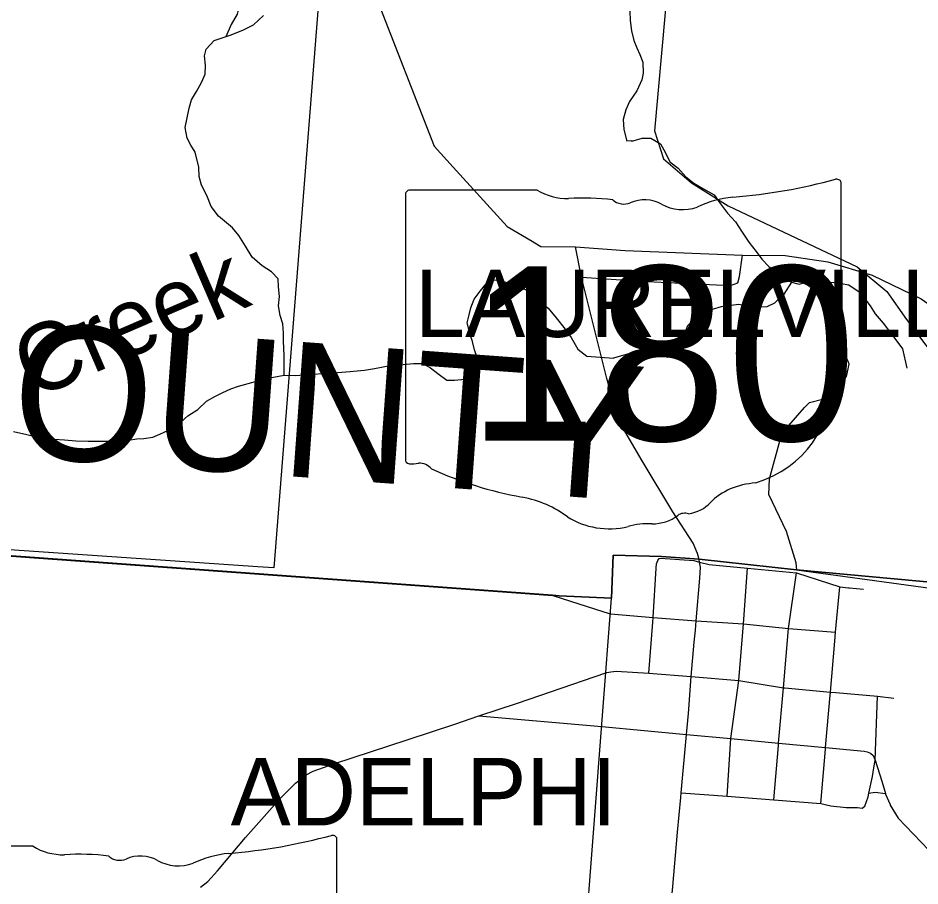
# Model space of a CAD drawing. Extents: x 0 to 42.5, y 0 to 22.
# Drawn here: x 7.502 to 8.135, y 15.405 to 16.014 of the extents above; entities that cross this region are included whole.
import ezdxf

# ---------------------------------------------------------------- set-up
doc = ezdxf.new("R2010")
doc.units = 0
for name, color, linetype in [('GM_X_City_Street', 7, 'Continuous'), ('GM_X_Corporation', 7, 'Continuous'), ('GM_X_Corporation_Text', 7, 'Continuous'), ('GM_X_County_Road', 7, 'Continuous'), ('GM_X_County_Text', 7, 'Continuous'), ('GM_X_Interchange_Ramps', 7, 'Continuous'), ('GM_X_Major_River', 7, 'Continuous'), ('GM_X_Minor_River', 7, 'Continuous'), ('GM_X_Minor_River_Text', 7, 'Continuous'), ('GM_X_Rail_Line', 7, 'Continuous'), ('GM_X_Section', 7, 'Continuous'), ('GM_X_State_Location', 7, 'Continuous'), ('GM_X_State_Route', 7, 'Continuous'), ('GM_X_State_Shield', 7, 'Continuous'), ('GM_X_Township', 7, 'Continuous'), ('GM_X_Township_Road', 7, 'Continuous'), ('SH_Cut_Line', 7, 'Continuous')]:
    doc.layers.add(name, color=color, linetype=linetype)

msp = doc.modelspace()

# ---------------------------------------------------------------- linework, layer by layer
at = {"layer": 'GM_X_City_Street'}
for points in [[(7.94946, 15.62782), (7.94964, 15.63083), (7.95056, 15.63326), (7.9517, 15.63451), (7.95243, 15.63492), (7.97602, 15.63321)], [(7.97602, 15.63321), (7.97995, 15.63207), (7.98677, 15.63034), (8.01368, 15.62775), (8.04805, 15.62451), (8.07833, 15.61475), (8.08456, 15.61412)], [(7.94425, 15.55408), (7.94725, 15.58987), (7.94745, 15.5932), (7.94946, 15.62782)], [(7.99931, 15.46769), (8.0019, 15.50818), (8.0074, 15.54903), (8.01084, 15.58864), (8.01368, 15.62775)], [(8.03206, 15.46517), (8.03532, 15.50341), (8.03545, 15.50498), (8.03876, 15.54379), (8.04231, 15.5855), (8.04805, 15.62451)], [(8.07483, 15.57664), (8.07537, 15.58282), (8.07833, 15.61475)], [(8.08456, 15.61412), (8.08508, 15.61407), (8.09512, 15.61305)], [(7.97758, 15.59076), (8.01084, 15.58864), (8.04231, 15.5855), (8.07537, 15.58282)], [(8.07155, 15.53864), (8.07174, 15.54083), (8.07483, 15.57664)], [(7.97399, 15.55167), (8.0074, 15.54903), (8.03876, 15.54379), (8.03974, 15.54371)], [(8.03974, 15.54371), (8.07174, 15.54083), (8.07559, 15.54048), (8.10479, 15.53785), (8.11637, 15.53655)], [(8.06499, 15.46264), (8.06827, 15.50064), (8.06837, 15.50184), (8.07155, 15.53864)], [(8.10237, 15.48771), (8.10308, 15.4916), (8.10313, 15.49293), (8.10479, 15.53785)], [(7.91137, 15.51661), (7.97081, 15.51115), (8.0019, 15.50818), (8.03545, 15.50498), (8.06837, 15.50184), (8.09556, 15.49924), (8.09764, 15.49898), (8.09988, 15.49796), (8.10172, 15.4962), (8.10313, 15.49293), (8.10795, 15.47835), (8.11036, 15.46966), (8.1105, 15.46915), (8.11366, 15.46188), (8.11385, 15.46146), (8.11924, 15.45237), (8.15691, 15.41289)], [(8.096, 15.4607), (8.0983, 15.46727), (8.09882, 15.46978), (8.10124, 15.4816), (8.10237, 15.48771)], [(7.96702, 15.47016), (7.99931, 15.46769), (8.03206, 15.46517), (8.06499, 15.46264), (8.07213, 15.46089), (8.08289, 15.45978), (8.09085, 15.45972), (8.09407, 15.45943), (8.096, 15.4607)], [(8.09882, 15.46978), (8.10315, 15.47053), (8.11036, 15.46966)]]:
    msp.add_lwpolyline(points, dxfattribs=at)
at = {"layer": 'GM_X_Corporation'}
msp.add_lwpolyline([(7.91921, 15.63683), (7.95331, 15.6361), (7.97957, 15.63417), (8.04805, 15.62672), (8.16418, 15.61064), (8.16271, 15.59296), (8.14602, 15.34154), (7.89922, 15.35961), (7.91813, 15.60669)], close=True, dxfattribs=at)
at = {"layer": 'GM_X_County_Road'}
for p, q in [((7.42284, 15.64165), (7.87685, 15.60852)), ((7.87685, 15.60852), (7.91279, 15.59711))]:
    msp.add_line(p, q, dxfattribs=at)
msp.add_lwpolyline([(7.91279, 15.59711), (7.91741, 15.59564), (7.94745, 15.5932), (7.97758, 15.59076)], dxfattribs=at)
at = {"layer": 'GM_X_Interchange_Ramps'}
msp.add_lwpolyline([(5.08492, 14.1), (8.06989, 14.1), (8.07009, 14.10263), (8.07289, 14.12804), (8.09551, 14.48695), (8.1568, 15.41315), (8.16884, 15.59509), (8.16995, 15.61544), (8.04805, 15.62672), (7.97957, 15.63417), (7.95331, 15.6361), (7.91921, 15.63683), (7.91813, 15.60669), (7.88151, 15.60844), (7.87674, 15.60879), (7.42273, 15.64192), (7.26665, 15.65331), (5.92916, 15.74982)], dxfattribs=at)
at = {"layer": 'GM_X_Major_River'}
for points in [[(7.68834, 15.76319), (7.68834, 15.76319), (7.68835, 15.77721), (7.68817, 15.78195), (7.688, 15.78746), (7.68801, 15.79277), (7.68745, 15.79923), (7.68557, 15.80512), (7.68445, 15.81196), (7.68503, 15.81841), (7.68429, 15.82524), (7.68412, 15.83094), (7.67958, 15.8359), (7.67295, 15.8401), (7.66595, 15.84621), (7.66122, 15.85383), (7.6565, 15.86125), (7.65215, 15.86678), (7.64231, 15.8748), (7.63721, 15.88166), (7.634, 15.88945), (7.63041, 15.89668), (7.62872, 15.90276), (7.62855, 15.90922), (7.62592, 15.91986), (7.6229, 15.92481), (7.62025, 15.92957), (7.61894, 15.93717), (7.62029, 15.94399), (7.62163, 15.95063), (7.62335, 15.95669), (7.62678, 15.96237), (7.63039, 15.96881), (7.63287, 15.97468), (7.63308, 15.98094), (7.63253, 15.98739), (7.63367, 15.99213), (7.63919, 15.99818), (7.64564, 16.00024), (7.65039, 16.00192), (7.65931, 16.00548), (7.6669, 16.00924), (7.67393, 16.01566)], [(7.68834, 15.76319), (7.69628, 15.76312), (7.70235, 15.76347), (7.70918, 15.76401), (7.71506, 15.76436), (7.72113, 15.76471), (7.72587, 15.76525), (7.73478, 15.76597), (7.73972, 15.76632), (7.74465, 15.76687), (7.75167, 15.76797), (7.7566, 15.7689), (7.76134, 15.76982), (7.76665, 15.77018), (7.77196, 15.77072), (7.77917, 15.77145), (7.78581, 15.7716), (7.79111, 15.76835), (7.79622, 15.76453), (7.80266, 15.75975), (7.80797, 15.75973), (7.81518, 15.76045), (7.82182, 15.7644), (7.8243, 15.7699), (7.82394, 15.77559), (7.82205, 15.7811), (7.82055, 15.787), (7.81905, 15.79194), (7.81679, 15.79992), (7.81813, 15.80561), (7.81947, 15.81054), (7.82176, 15.8166), (7.82594, 15.82227), (7.83013, 15.82738), (7.83601, 15.83019), (7.84265, 15.82902), (7.84814, 15.82691), (7.85364, 15.82536)], [(8.04448, 15.82849), (8.03905, 15.82019), (8.03256, 15.81378), (8.02724, 15.81116), (8.0208, 15.81101), (8.01284, 15.81182), (8.00755, 15.8128), (8.00186, 15.81227), (7.99503, 15.81136), (7.98877, 15.8095), (7.98231, 15.80708), (7.97717, 15.8037), (7.97145, 15.79804), (7.96952, 15.79293), (7.96644, 15.78687), (7.96223, 15.77988), (7.95746, 15.77573), (7.95123, 15.77881), (7.94517, 15.77961), (7.94044, 15.77945), (7.93512, 15.77853), (7.93001, 15.77819), (7.91955, 15.77525)], [(8.04448, 15.82849), (8.04989, 15.82715), (8.05692, 15.829), (8.06185, 15.82935), (8.06752, 15.82855), (8.07415, 15.82832), (8.07926, 15.82753), (8.08475, 15.82673), (8.09192, 15.82175), (8.09605, 15.81679), (8.09981, 15.81202), (8.10318, 15.80631), (8.10882, 15.79982), (8.11257, 15.79486), (8.11708, 15.78895), (8.12234, 15.7817), (8.12532, 15.76819)], [(7.85364, 15.82536), (7.85951, 15.82249), (7.86613, 15.81657), (7.8737, 15.81027), (7.87919, 15.8036), (7.88562, 15.7956), (7.88977, 15.78969), (7.8945, 15.78151), (7.90093, 15.77654), (7.91955, 15.77525)]]:
    msp.add_lwpolyline(points, dxfattribs=at)
at = {"layer": 'GM_X_Minor_River'}
for points in [[(7.61942, 16.13987), (7.62432, 16.1277), (7.62601, 16.11858), (7.62713, 16.11136), (7.62787, 16.10509), (7.62748, 16.09845), (7.62727, 16.092), (7.62707, 16.08517), (7.62762, 16.07871), (7.62836, 16.07207), (7.63081, 16.06579), (7.63422, 16.06065), (7.6399, 16.05683), (7.64595, 16.05243), (7.65182, 16.04576), (7.65389, 16.04024), (7.65577, 16.03511), (7.65747, 16.02998), (7.65707, 16.02315), (7.65535, 16.0167), (7.65116, 16.00951), (7.64739, 16.00086)], [(7.9221, 16.06196), (7.92453, 16.05625), (7.9277, 16.04959), (7.92861, 16.04427), (7.92952, 16.03819), (7.93023, 16.03155), (7.93113, 16.02395), (7.93109, 16.01883), (7.93123, 16.01218), (7.93213, 16.00496), (7.93379, 15.99831), (7.93584, 15.99317), (7.93808, 15.98842), (7.94013, 15.9829), (7.94045, 15.9753), (7.93947, 15.97057), (7.93582, 15.963), (7.93084, 15.95544), (7.92815, 15.94957), (7.9264, 15.94275), (7.92673, 15.93573), (7.92889, 15.92758)], [(7.93195, 15.9278), (7.93331, 15.9279), (7.93976, 15.92957), (7.94582, 15.92972), (7.95262, 15.92569), (7.95598, 15.91941), (7.95916, 15.91294), (7.96501, 15.90872), (7.97027, 15.90262), (7.97592, 15.89803), (7.98271, 15.894), (7.99026, 15.88977), (7.99458, 15.88367), (7.99946, 15.877), (8.0051, 15.87089), (8.00942, 15.86441), (8.01448, 15.8566), (8.01974, 15.85011), (8.02368, 15.84477), (8.02857, 15.83962), (8.03517, 15.83483), (8.04448, 15.82849)], [(7.93195, 15.9278), (7.92888, 15.92764)], [(7.68809, 15.77007), (7.6881, 15.76994)], [(7.4984, 15.72366), (7.50768, 15.72172), (7.51621, 15.71959), (7.52171, 15.7188), (7.52683, 15.7184), (7.53422, 15.71779), (7.54219, 15.71719), (7.55091, 15.71695), (7.56703, 15.71687), (7.57253, 15.71704), (7.57917, 15.71776), (7.58486, 15.7185), (7.58998, 15.71885), (7.59624, 15.71977), (7.60118, 15.72183), (7.60725, 15.72465), (7.61333, 15.72785), (7.62074, 15.73483), (7.62777, 15.73916), (7.63385, 15.74502), (7.63973, 15.74821), (7.64524, 15.75122), (7.65094, 15.75366), (7.65625, 15.75553), (7.66821, 15.75889), (7.67447, 15.76076), (7.68834, 15.76319)]]:
    msp.add_lwpolyline(points, dxfattribs=at)
at = {"layer": 'GM_X_Rail_Line'}
msp.add_lwpolyline([(7.98347, 16.32444), (7.94829, 15.9349), (7.95454, 15.91522), (7.97421, 15.89822), (8.00014, 15.88211), (8.09048, 15.83928), (8.11148, 15.82198), (8.12531, 15.80248), (8.17938, 15.73019)], dxfattribs=at)
at = {"layer": 'GM_X_Section'}
msp.add_lwpolyline([(7.2242, 16.15625), (7.72073, 16.1288), (7.68116, 15.62804), (7.66979, 15.62881), (7.18785, 15.66177)], close=True, dxfattribs=at)
at = {"layer": 'GM_X_State_Route'}
for p, q in [((7.97399, 15.55167), (7.97626, 15.57598)), ((7.94425, 15.55408), (7.97399, 15.55167))]:
    msp.add_line(p, q, dxfattribs=at)
for points in [[(7.75232, 16.03057), (7.79365, 15.92412), (7.80709, 15.90931), (7.84493, 15.86762), (7.86234, 15.85729), (7.86725, 15.85438)], [(7.86725, 15.85438), (7.86859, 15.85359), (7.89288, 15.85342)], [(7.89288, 15.85342), (7.92764, 15.85091), (8.00999, 15.84744)], [(7.97968, 15.63391), (7.9785, 15.63813), (7.97548, 15.64526), (7.9611, 15.66733), (7.93969, 15.70315), (7.92761, 15.72392), (7.92104, 15.73981), (7.91489, 15.76101), (7.89712, 15.83218), (7.89288, 15.85342)], [(8.00999, 15.84744), (8.04008, 15.84735), (8.07009, 15.84292), (8.10108, 15.83357), (8.13551, 15.81685), (8.15807, 15.80127), (8.17068, 15.79387), (8.17944, 15.79084)], [(7.97626, 15.57598), (7.97703, 15.58424), (7.97758, 15.59076), (7.98013, 15.62077), (7.98061, 15.6284), (7.97995, 15.63207), (7.97968, 15.63391)], [(7.62966, 15.40399), (7.63485, 15.40788), (7.6416, 15.41541), (7.66132, 15.43877), (7.68546, 15.46602), (7.69636, 15.47692), (7.70389, 15.48263), (7.70882, 15.48523), (7.72335, 15.49042), (7.77552, 15.50755), (7.80823, 15.51832), (7.8251, 15.52416), (7.85209, 15.53312), (7.91425, 15.55439), (7.91475, 15.55449)], [(7.91475, 15.55449), (7.91773, 15.55511), (7.92152, 15.55557), (7.94425, 15.55408)], [(7.96671, 15.46671), (7.96702, 15.47016), (7.97081, 15.51115), (7.97217, 15.52569), (7.97399, 15.55167)], [(7.95958, 15.38697), (7.96119, 15.40436), (7.96454, 15.44253), (7.96671, 15.46671)]]:
    msp.add_lwpolyline(points, dxfattribs=at)
at = {"layer": 'GM_X_State_Shield'}
for p, q in [((8.07931, 15.80065), (8.07931, 15.89779)), ((7.7735, 15.88999), (7.7735, 15.7043)), ((7.86606, 15.89319), (7.77651, 15.89319)), ((8.07928, 15.80068), (8.07931, 15.80065)), ((7.72545, 15.34002), (7.72545, 15.43715)), ((7.51221, 15.43255), (7.42265, 15.43255))]:
    msp.add_line(p, q, dxfattribs=at)
for centre, major_axis, start_param, end_param in [((7.97037, 16.14634), (0.32431, 0), 4.814394, 5.042369), ((8.07591, 15.89819), (0.0034, 0), 6.141152, 7.989035), ((7.777, 15.89039), (0.00354, 0), 1.712693, 3.28349), ((7.88739, 15.91474), (0.03436, 0), 4.042523, 4.731795), ((7.89879, 15.78894), (0.12336, 0), 1.404758, 1.657858), ((7.92679, 15.89135), (0.00991, 0), 3.836095, 5.185415), ((7.94135, 15.86989), (0.02061, 0), 0.950623, 2.079405), ((8.01174, 15.83647), (0.06525, 0), 1.699011, 2.107814), ((7.96795, 15.89932), (0.02479, 0), 4.081561, 5.145723), ((8.07852, 15.79352), (0.00527, 0), 1.883978, 3.671073), ((8.07567, 15.80028), (0.00364, 0), 5.05454, 6.418171), ((8.045, 15.78124), (0.03163, 0), 5.934695, 6.695948), ((8.0915, 15.76), (0.02301, 0), 2.387724, 3.262537), ((7.98854, 15.74765), (0.08112, 0), 5.101752, 6.440018), ((7.77703, 15.7039), (0.00357, 0), 3.00124, 4.508301), ((7.77757, 15.7229), (0.02728, 0), 4.665946, 4.897461), ((7.78315, 15.69359), (0.00984, 0), 0.519207, 1.627899), ((7.90733, 15.86042), (0.2342, 0), 4.195997, 4.488961), ((8.02274, 15.65217), (0.04443, 0), 1.647645, 2.488434), ((7.8375, 15.62088), (0.07328, 0), 0.823519, 1.323587), ((7.96645, 15.68631), (0.02621, 0), 4.937069, 5.64225), ((7.91675, 15.69267), (0.0465, 0), 4.026481, 4.996735), ((7.94702, 15.67877), (0.02477, 0), 4.691044, 5.507374), ((7.96943, 15.66078), (0.00698, 0), 1.147584, 2.315152), ((7.94362, 15.62847), (0.03821, 0), 1.495662, 1.94098), ((7.61652, 15.6857), (0.32431, 0), 4.814394, 5.042369), ((7.72206, 15.43755), (0.0034, 0), 6.141152, 7.989035), ((7.53354, 15.45411), (0.03436, 0), 4.042523, 4.731795), ((7.54493, 15.3283), (0.12336, 0), 1.404758, 1.657858), ((7.57294, 15.43071), (0.00991, 0), 3.836095, 5.185415), ((7.58749, 15.40925), (0.02061, 0), 0.950623, 2.079405), ((7.6141, 15.43869), (0.02479, 0), 4.081561, 5.145723), ((7.65789, 15.37584), (0.06525, 0), 1.699011, 2.107814)]:
    msp.add_ellipse(centre, major_axis=major_axis, ratio=0.8, start_param=start_param, end_param=end_param, dxfattribs=at)
at = {"layer": 'GM_X_Township'}
msp.add_lwpolyline([(8.24781, 16.59008), (8.17933, 15.79111), (8.17776, 15.76158), (8.17561, 15.72139), (8.1727, 15.66691), (8.17075, 15.63044), (8.16995, 15.61544), (8.04805, 15.62672), (7.97957, 15.63417), (7.95331, 15.6361), (7.91921, 15.63683), (7.91813, 15.60669), (7.88151, 15.60844), (7.87674, 15.60879), (7.42273, 15.64192), (7.26665, 15.65331), (5.92916, 15.74982), (5.21422, 15.79865), (5.23885, 16.11392)], dxfattribs=at)
at = {"layer": 'GM_X_Township_Road'}
msp.add_line((7.8251, 15.52416), (7.91137, 15.51661), dxfattribs=at)
for points in [[(7.96715, 15.82789), (8.00157, 15.82613), (8.00689, 15.82816), (8.00789, 15.83252), (8.00999, 15.84744)], [(7.89712, 15.83218), (7.93872, 15.82935), (7.96715, 15.82789)], [(8.04816, 15.62645), (8.04784, 15.63153), (8.04103, 15.65358), (8.02853, 15.67959), (8.02902, 15.69059), (8.03649, 15.71785), (8.04093, 15.72615), (8.05357, 15.74065), (8.05701, 15.74403), (8.06708, 15.74679), (8.08314, 15.76239), (8.08493, 15.77092), (8.08364, 15.77453), (8.07918, 15.78235)]]:
    msp.add_lwpolyline(points, dxfattribs=at)
at = {"layer": 'SH_Cut_Line'}
for points in [[(3.72132, 15.90374), (4.44374, 15.85348), (4.57597, 15.84389), (4.70326, 15.83465), (4.83401, 15.82463), (5.0466, 15.8101), (5.21422, 15.79865), (5.92916, 15.74982), (7.26665, 15.65331), (7.42273, 15.64192), (7.87674, 15.60879), (7.88151, 15.60844), (7.91813, 15.60669), (7.91921, 15.63683), (7.95331, 15.6361), (7.97957, 15.63417), (8.04805, 15.62672), (8.16995, 15.61544), (8.17075, 15.63044), (8.1727, 15.66691), (8.17561, 15.72139), (8.17776, 15.76158), (8.17933, 15.79111), (8.24781, 16.59008)], [(2.1, 14.1), (8.06989, 14.1), (8.07009, 14.10263), (8.07289, 14.12804), (8.09551, 14.48695), (8.1568, 15.41315), (8.16884, 15.59509), (8.16995, 15.61544), (8.04805, 15.62672), (7.97957, 15.63417), (7.95331, 15.6361), (7.91921, 15.63683), (7.91813, 15.60669), (7.88151, 15.60844), (7.87674, 15.60879), (7.42273, 15.64192), (7.26665, 15.65331), (5.92916, 15.74982)]]:
    msp.add_lwpolyline(points, dxfattribs=at)

# ---------------------------------------------------------------- texts
at = {"layer": 'GM_X_Corporation_Text'}
for s, height, p in [('LAURELVILLE', 0.0473485, (7.78018, 15.7901)), ('ADELPHI', 0.047348, (7.65078, 15.44719))]:
    msp.add_text(s, height=height, rotation=0.00001, dxfattribs=at).set_placement(p)
at = {"layer": 'GM_X_County_Text'}
msp.add_text('PICKAWAY COUNTY', height=0.094697, rotation=355.85295, dxfattribs=at).set_placement((6.70196, 15.76412))
at = {"layer": 'GM_X_Minor_River_Text'}
msp.add_text('Creek', height=0.047347, rotation=23.37645, dxfattribs=at).set_placement((7.51171, 15.74585))
at = {"layer": 'GM_X_State_Location'}
for s in ['s', 'r']:
    msp.add_text(s, height=0.0000947, dxfattribs=at).set_placement((7.91712, 15.72478))
msp.add_text('180', height=0.0000947, rotation=0.00001, dxfattribs=at).set_placement((7.88369, 15.71789))
at = {"layer": 'GM_X_State_Shield'}
msp.add_text('180', height=0.122327, dxfattribs=at).set_placement((7.81706, 15.7174))

doc.saveas('drawing.dxf')
